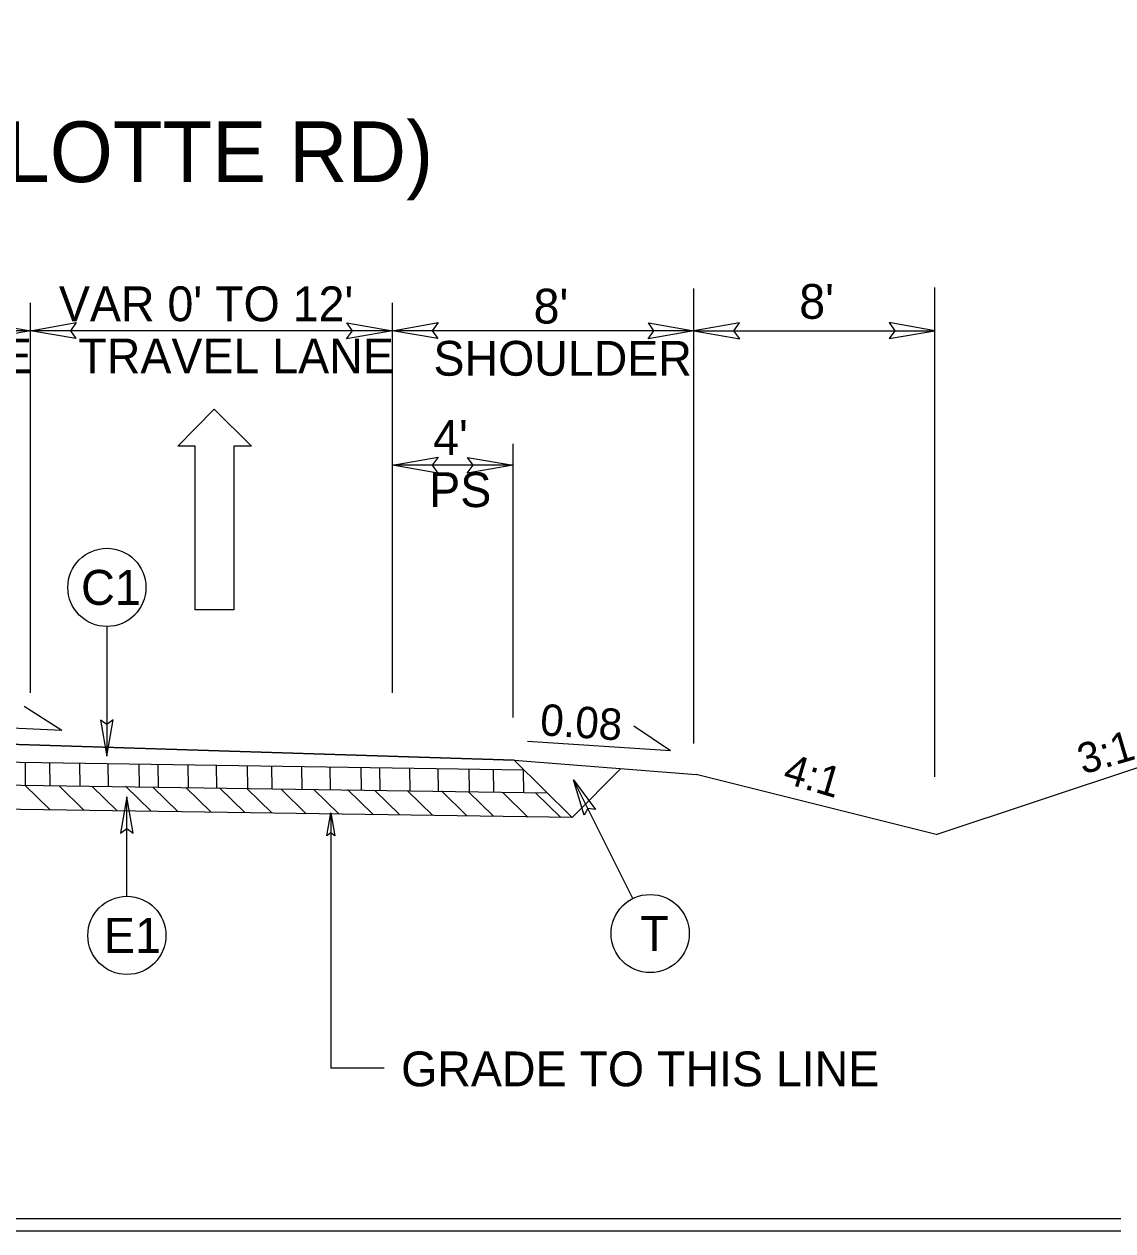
# Model space of a CAD drawing. Extents: x 2176024 to 2177225, y 75947 to 76635.
# Drawn here: x 2176790.13 to 2176826.22, y 76458.07 to 76498.08 of the extents above; entities that cross this region are included whole.
import ezdxf

# ---------------------------------------------------------------- set-up
doc = ezdxf.new("R2010")
doc.units = 0
for name, color, linetype in [('Old_Level_1', 7, 'Continuous'), ('Old_Level_11', 7, 'Continuous'), ('Old_Level_4', 7, 'Continuous'), ('Prop Dimension', 7, 'Continuous'), ('Sheet Plot Border Inside CELL', 7, 'Continuous'), ('Sheet Typical CELL', 7, 'Continuous'), ('Typical Curb CELL', 7, 'Continuous'), ('Typical Pavement Slope CELL', 7, 'Continuous'), ('Typical Pavement Slope Information CELL', 7, 'Continuous'), ('Typical Shoulder Slope CELL', 7, 'Continuous'), ('Typical Slope Point Local CELL', 7, 'Continuous'), ('Typical Terminator CELL', 7, 'Continuous'), ('Typical Text General CELL', 7, 'Continuous'), ('Typical Text Label CELL', 7, 'Continuous')]:
    doc.layers.add(name, color=color, linetype=linetype)

msp = doc.modelspace()

# ---------------------------------------------------------------- linework, layer by layer
at = {"layer": 'Old_Level_1'}
for p, q in [((2176790.176, 76472.848), (2176790.166, 76473.604)), ((2176790.99, 76472.836), (2176790.979, 76473.592)), ((2176791.987, 76472.815), (2176791.976, 76473.577)), ((2176792.928, 76472.807), (2176792.917, 76473.563)), ((2176793.946, 76472.792), (2176793.935, 76473.548)), ((2176794.582, 76472.783), (2176794.571, 76473.538)), ((2176795.579, 76472.768), (2176795.568, 76473.523)), ((2176796.52, 76472.754), (2176796.509, 76473.509)), ((2176797.538, 76472.739), (2176797.527, 76473.494)), ((2176798.351, 76472.726), (2176798.34, 76473.482)), ((2176799.349, 76472.705), (2176799.338, 76473.467)), ((2176800.289, 76472.698), (2176800.278, 76473.453)), ((2176801.307, 76472.682), (2176801.296, 76473.438)), ((2176801.933, 76472.673), (2176801.922, 76473.429)), ((2176802.93, 76472.658), (2176802.919, 76473.414)), ((2176803.87, 76472.644), (2176803.859, 76473.4)), ((2176804.888, 76472.629), (2176804.877, 76473.385)), ((2176805.702, 76472.617), (2176805.691, 76473.373)), ((2176806.699, 76472.596), (2176806.688, 76473.358)), ((2176790.977, 76472.035), (2176790.15, 76472.846)), ((2176792.117, 76472.003), (2176791.282, 76472.822)), ((2176793.207, 76471.994), (2176792.372, 76472.813)), ((2176794.326, 76471.991), (2176793.491, 76472.809)), ((2176795.22, 76471.972), (2176794.393, 76472.782)), ((2176796.325, 76471.948), (2176795.49, 76472.767)), ((2176797.444, 76471.944), (2176796.609, 76472.763)), ((2176798.338, 76471.926), (2176797.511, 76472.736)), ((2176799.478, 76471.893), (2176798.643, 76472.712)), ((2176800.568, 76471.885), (2176799.733, 76472.704)), ((2176801.688, 76471.881), (2176800.852, 76472.7)), ((2176802.581, 76471.863), (2176801.754, 76472.673)), ((2176803.676, 76471.839), (2176802.84, 76472.657)), ((2176804.795, 76471.835), (2176803.96, 76472.654)), ((2176805.688, 76471.816), (2176804.862, 76472.627)), ((2176806.829, 76471.784), (2176805.993, 76472.603)), ((2176807.919, 76471.775), (2176807.084, 76472.594))]:
    msp.add_line(p, q, dxfattribs=at)
at = {"layer": 'Old_Level_11'}
for p, q in [((2176792.87, 76478.108), (2176792.87, 76473.805)), ((2176810.304, 76469.085), (2176808.341, 76473.021)), ((2176793.533, 76469.161), (2176793.533, 76472.457))]:
    msp.add_line(p, q, dxfattribs=at)
for points in [[(2176792.663, 76475.005), (2176792.87, 76473.805), (2176793.083, 76475.012), (2176792.87, 76474.859)], [(2176808.691, 76471.855), (2176808.341, 76473.021), (2176809.07, 76472.036), (2176808.811, 76472.078)], [(2176793.74, 76471.257), (2176793.533, 76472.457), (2176793.32, 76471.251), (2176793.533, 76471.404)]]:
    msp.add_lwpolyline(points, close=True, dxfattribs=at)
for centre in [(2176792.87, 76479.404), (2176793.533, 76467.865), (2176810.882, 76467.925)]:
    msp.add_circle(centre, 1.296, dxfattribs=at)
at = {"layer": 'Old_Level_4'}
for p, q in [((2176795.22, 76484.092), (2176796.423, 76485.314)), ((2176796.423, 76485.314), (2176797.665, 76484.092)), ((2176795.802, 76484.092), (2176795.22, 76484.092)), ((2176795.802, 76478.66), (2176795.802, 76484.092)), ((2176797.665, 76484.092), (2176797.083, 76484.092)), ((2176797.083, 76484.092), (2176797.083, 76478.66)), ((2176797.083, 76478.66), (2176795.802, 76478.66))]:
    msp.add_line(p, q, dxfattribs=at)
at = {"layer": 'Prop Dimension'}
for p, q in [((2176812.335, 76474.225), (2176812.335, 76489.312)), ((2176820.322, 76473.119), (2176820.322, 76489.35)), ((2176790.335, 76475.904), (2176790.335, 76488.844)), ((2176802.335, 76475.904), (2176802.335, 76488.844)), ((2176790.335, 76487.916), (2176778.335, 76487.916)), ((2176802.335, 76487.916), (2176790.335, 76487.916)), ((2176812.335, 76487.916), (2176802.335, 76487.916)), ((2176812.335, 76487.916), (2176820.322, 76487.916)), ((2176806.335, 76475.09), (2176806.335, 76484.165)), ((2176806.335, 76483.456), (2176802.335, 76483.456)), ((2176800.296, 76471.891), (2176800.296, 76463.466)), ((2176802.063, 76463.466), (2176800.296, 76463.466))]:
    msp.add_line(p, q, dxfattribs=at)
at = {"layer": 'Sheet Plot Border Inside CELL'}
msp.add_lwpolyline([(2176897.987, 76626.883), (2176631.347, 76626.883), (2176631.347, 76458.067), (2176897.987, 76458.067)], close=True, dxfattribs=at)
at = {"layer": 'Sheet Typical CELL'}
msp.add_lwpolyline([(2176895.987, 76626.475), (2176655.987, 76626.475), (2176655.987, 76458.475), (2176895.987, 76458.475)], close=True, dxfattribs=at)
at = {"layer": 'Typical Curb CELL'}
for q in [(2176809.915, 76473.395), (2176786.517, 76472.096)]:
    msp.add_line((2176808.293, 76471.772), q, dxfattribs=at)
at = {"layer": 'Typical Pavement Slope CELL'}
for p, q in [((2176786.517, 76473.658), (2176806.698, 76473.358)), ((2176806.376, 76473.678), (2176808.293, 76471.772)), ((2176786.517, 76472.903), (2176807.469, 76472.591))]:
    msp.add_line(p, q, dxfattribs=at)
at = {"layer": 'Typical Pavement Slope Information CELL'}
for p, q in [((2176791.371, 76474.664), (2176790.131, 76475.46)), ((2176791.371, 76474.664), (2176783.873, 76475.014)), ((2176811.562, 76473.98), (2176810.338, 76474.799)), ((2176811.562, 76473.98), (2176806.816, 76474.294))]:
    msp.add_line(p, q, dxfattribs=at)
at = {"layer": 'Typical Shoulder Slope CELL'}
for p, q in [((2176820.363, 76471.207), (2176828.008, 76473.755)), ((2176806.376, 76473.678), (2176812.411, 76473.195)), ((2176820.363, 76471.207), (2176812.411, 76473.195))]:
    msp.add_line(p, q, dxfattribs=at)
at = {"layer": 'Typical Slope Point Local CELL'}
for p, q in [((2176778.335, 76474.553), (2176806.376, 76473.678)), ((2176806.376, 76473.678), (2176778.335, 76474.553)), ((2176786.517, 76473.658), (2176806.698, 76473.358)), ((2176806.698, 76473.358), (2176806.376, 76473.678))]:
    msp.add_line(p, q, dxfattribs=at)
at = {"layer": 'Typical Terminator CELL'}
for points in [[(2176788.825, 76488.176), (2176790.335, 76487.916), (2176788.817, 76487.648), (2176789.009, 76487.916)], [(2176791.844, 76487.656), (2176790.335, 76487.916), (2176791.853, 76488.184), (2176791.66, 76487.916)], [(2176800.825, 76488.176), (2176802.335, 76487.916), (2176800.817, 76487.648), (2176801.009, 76487.916)], [(2176803.844, 76487.656), (2176802.335, 76487.916), (2176803.853, 76488.184), (2176803.66, 76487.916)], [(2176810.825, 76488.176), (2176812.335, 76487.916), (2176810.817, 76487.648), (2176811.009, 76487.916)], [(2176813.844, 76488.176), (2176812.335, 76487.916), (2176813.853, 76487.648), (2176813.66, 76487.916)], [(2176818.812, 76487.656), (2176820.322, 76487.916), (2176818.804, 76488.184), (2176818.997, 76487.916)], [(2176803.844, 76483.196), (2176802.335, 76483.456), (2176803.853, 76483.724), (2176803.66, 76483.456)], [(2176804.825, 76483.716), (2176806.335, 76483.456), (2176804.817, 76483.187), (2176805.009, 76483.456)], [(2176800.166, 76471.169), (2176800.296, 76471.924), (2176800.43, 76471.165), (2176800.296, 76471.262)]]:
    msp.add_lwpolyline(points, close=True, dxfattribs=at)

# ---------------------------------------------------------------- texts
at = {"layer": 'Old_Level_11'}
for s, rotation, p in [('C1', 359.9997, (2176792.013, 76478.824)), ('T', 0.0003, (2176810.555, 76467.345)), ('E1', 359.9997, (2176792.769, 76467.285))]:
    msp.add_text(s, height=1.16, rotation=rotation, dxfattribs=at).set_placement(p)
at = {"layer": 'Typical Pavement Slope Information CELL'}
msp.add_text('0.08', height=1.0429, rotation=356.2199, dxfattribs=at).set_placement((2176807.212, 76474.504))
at = {"layer": 'Typical Slope Point Local CELL'}
for s, rotation, p in [('3:1', 16.4649, (2176825.23, 76473.195)), ('4:1', 343.5351, (2176815.239, 76472.944))]:
    msp.add_text(s, height=1.0064, rotation=rotation, dxfattribs=at).set_placement(p)
at = {"layer": 'Typical Text General CELL'}
for s, height, p in [("VAR 0' TO 12'", 1.15334, (2176791.279, 76488.232)), ("8' ", 1.1533, (2176807.017, 76488.154)), ("8'", 1.1533, (2176815.825, 76488.311)), ('TRAVEL LANE', 1.15334, (2176779.925, 76486.502)), ('TRAVEL LANE', 1.15334, (2176791.925, 76486.502)), ('SHOULDER', 1.1533, (2176803.697, 76486.424)), ("4' ", 1.1533, (2176803.687, 76483.797)), ('PS', 1.1533, (2176803.558, 76482.067)), ('GRADE TO THIS LINE', 1.15334, (2176802.626, 76462.862))]:
    msp.add_text(s, height=height, dxfattribs=at).set_placement(p)
at = {"layer": 'Typical Text Label CELL'}
msp.add_text('C -Y- (OLD SHALLOTTE RD)', height=2.01314, dxfattribs=at).set_placement((2176768.239, 76492.843))

doc.saveas('drawing.dxf')
